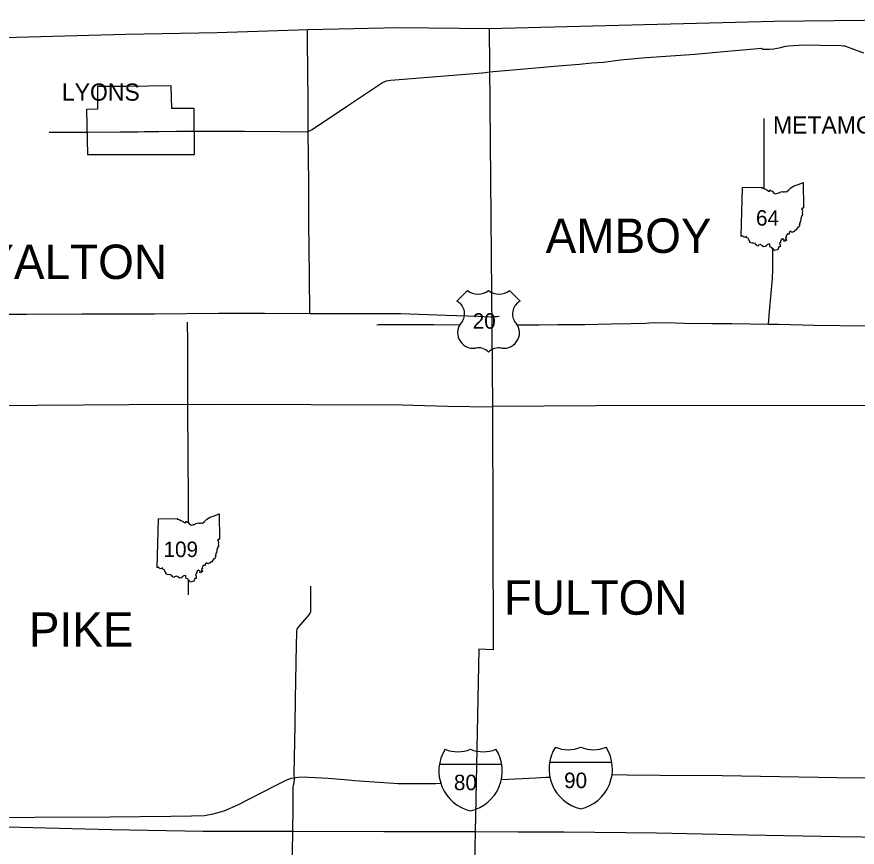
# Model space of a CAD drawing. Extents: x -232 to 448, y 619 to 1059.
# Drawn here: x 17.9 to 68.1, y 907.4 to 957 of the extents above; entities that cross this region are included whole.
import ezdxf

# ---------------------------------------------------------------- set-up
doc = ezdxf.new("R2010")
doc.units = 0
doc.layers.add('Default', color=7, linetype='Continuous')

msp = doc.modelspace()

# ---------------------------------------------------------------- linework, layer by layer
at = {"layer": 'Default'}
for p, q in [((61.207, 943.835), (61.289, 946.764)), ((61.207, 943.835), (61.289, 946.764)), ((44.856, 940.619), (44.222, 939.985)), ((44.856, 940.619), (44.222, 939.985)), ((48.012, 939.985), (47.377, 940.619)), ((48.012, 939.985), (47.377, 940.619)), ((26.318, 924.047), (26.4, 926.976)), ((26.318, 924.047), (26.4, 926.976)), ((43.182, 912.333), (46.902, 912.333)), ((49.765, 912.456), (53.486, 912.456))]:
    msp.add_line(p, q, dxfattribs=at)
for points in [[(46.162, 956.25), (63.186, 956.696), (68.56, 956.753), (73.967, 956.956), (79.258, 956.939)], [(13.563, 955.63), (24.424, 955.929), (29.905, 956.011), (35.341, 956.203), (40.766, 956.311), (46.162, 956.25)], [(35.432, 939.244), (35.416, 941.492), (35.389, 944.667), (35.385, 946.985), (35.348, 950.103), (35.345, 951.921), (35.293, 955.53), (35.297, 956.202)], [(46.162, 956.25), (46.355, 933.706)], [(45.931, 953.639), (46.146, 953.666), (47.115, 953.752), (48.94, 953.916), (50.044, 954.004), (51.547, 954.133), (52.282, 954.199), (52.978, 954.249), (54.005, 954.393), (55.537, 954.524), (57.009, 954.628), (58.442, 954.735), (60.391, 954.902), (61.773, 955.025), (62.425, 955.086), (62.443, 955.057), (62.483, 955.033), (62.582, 955.024), (62.663, 955.025)], [(62.663, 955.025), (62.903, 955.025), (63.13, 955.046), (63.576, 955.123), (63.784, 955.175)], [(63.784, 955.175), (63.883, 955.199), (64.007, 955.218), (64.652, 955.27), (64.823, 955.279), (65.934, 955.264), (67.19, 955.243), (67.317, 955.229), (67.375, 955.221), (67.444, 955.198), (68.507, 954.806)], [(35.348, 950.103), (35.585, 950.225), (37.625, 951.605), (39.296, 952.722), (39.778, 953.029), (40.014, 953.133), (40.268, 953.172), (40.768, 953.216), (45.739, 953.614), (45.931, 953.639)], [(24.442, 952.798), (22.757, 952.796), (22.758, 951.433)], [(27.155, 952.839), (24.442, 952.798)], [(28.555, 948.739), (28.528, 951.49), (27.193, 951.475), (27.155, 952.839)], [(22.758, 951.433), (22.098, 951.427), (22.151, 948.731)], [(62.591, 946.734), (62.576, 949.299), (62.577, 950.888), (62.577, 950.894)], [(19.871, 950.071), (21.657, 950.076), (22.124, 950.078)], [(22.124, 950.078), (24.103, 950.085), (25.171, 950.096)], [(25.171, 950.096), (25.552, 950.1)], [(25.552, 950.1), (25.825, 950.103), (26.04, 950.105)], [(26.04, 950.105), (26.417, 950.109)], [(26.417, 950.109), (27.466, 950.119), (28.569, 950.132)], [(28.569, 950.132), (29.048, 950.138), (31.528, 950.123), (33.646, 950.109), (35.175, 950.088), (35.348, 950.103)], [(22.151, 948.731), (28.555, 948.739)], [(61.289, 946.764), (62.425, 946.783), (62.408, 946.747), (62.515, 946.74), (62.629, 946.677), (62.725, 946.638), (62.843, 946.545), (62.913, 946.546), (62.943, 946.622), (62.997, 946.563), (63.061, 946.553), (63.172, 946.412), (63.263, 946.382), (63.373, 946.43), (63.455, 946.438), (63.515, 946.485), (63.671, 946.526), (63.714, 946.502), (63.797, 946.507), (63.838, 946.525), (63.91, 946.509), (64.037, 946.615), (64.168, 946.741), (64.368, 946.859), (64.668, 946.971), (64.905, 947.072), (64.939, 945.552)], [(61.289, 946.764), (62.425, 946.783), (62.408, 946.747), (62.515, 946.74), (62.629, 946.677), (62.725, 946.638), (62.843, 946.545), (62.913, 946.546), (62.943, 946.622), (62.997, 946.563), (63.061, 946.553), (63.172, 946.412), (63.263, 946.382), (63.373, 946.43), (63.455, 946.438), (63.515, 946.485), (63.671, 946.526), (63.714, 946.502), (63.797, 946.507), (63.838, 946.525), (63.91, 946.509), (64.037, 946.615), (64.168, 946.741), (64.368, 946.859), (64.668, 946.971), (64.905, 947.072), (64.939, 945.552)], [(64.939, 945.552), (64.904, 945.53), (64.85, 945.54), (64.813, 945.498), (64.859, 945.427), (64.88, 945.352), (64.861, 945.269), (64.88, 945.2), (64.867, 945.143), (64.833, 945.086), (64.821, 945.032), (64.792, 944.975), (64.794, 944.943), (64.766, 944.918), (64.772, 944.823), (64.757, 944.77), (64.762, 944.724), (64.717, 944.713), (64.728, 944.675), (64.699, 944.646), (64.705, 944.596), (64.673, 944.564), (64.704, 944.5), (64.679, 944.48), (64.658, 944.403), (64.6, 944.387), (64.485, 944.245), (64.444, 944.192), (64.398, 944.178), (64.373, 944.123), (64.316, 944.123), (64.231, 944.085), (64.176, 944.15), (64.079, 944.071), (64.068, 943.98), (63.946, 943.983), (63.951, 943.937), (63.923, 943.923), (63.898, 943.877), (63.913, 943.795), (63.856, 943.774), (63.863, 943.726), (63.899, 943.697), (63.915, 943.606), (63.855, 943.624), (63.805, 943.547), (63.754, 943.565), (63.77, 943.631), (63.684, 943.709), (63.602, 943.646), (63.559, 943.546), (63.559, 943.478), (63.498, 943.438), (63.537, 943.342), (63.53, 943.277), (63.531, 943.215), (63.454, 943.217), (63.408, 943.049)], [(64.939, 945.552), (64.904, 945.53), (64.85, 945.54), (64.813, 945.498), (64.859, 945.427), (64.88, 945.352), (64.861, 945.269), (64.88, 945.2), (64.867, 945.143), (64.833, 945.086), (64.821, 945.032), (64.792, 944.975), (64.794, 944.943), (64.766, 944.918), (64.772, 944.823), (64.757, 944.77), (64.762, 944.724), (64.717, 944.713), (64.728, 944.675), (64.699, 944.646), (64.705, 944.596), (64.673, 944.564), (64.704, 944.5), (64.679, 944.48), (64.658, 944.403), (64.6, 944.387), (64.485, 944.245), (64.444, 944.192), (64.398, 944.178), (64.373, 944.123), (64.316, 944.123), (64.231, 944.085), (64.176, 944.15), (64.079, 944.071), (64.068, 943.98), (63.946, 943.983), (63.951, 943.937), (63.923, 943.923), (63.898, 943.877), (63.913, 943.795), (63.856, 943.774), (63.863, 943.726), (63.899, 943.697), (63.915, 943.606), (63.855, 943.624), (63.805, 943.547), (63.754, 943.565), (63.77, 943.631), (63.684, 943.709), (63.602, 943.646), (63.559, 943.546), (63.559, 943.478), (63.498, 943.438), (63.537, 943.342), (63.53, 943.277), (63.531, 943.215), (63.454, 943.217), (63.408, 943.049)], [(63.408, 943.049), (63.276, 943.016), (63.184, 942.997), (63.151, 943.074), (63.085, 943.114), (63.042, 943.191), (62.948, 943.201), (62.926, 943.307), (62.915, 943.393), (62.786, 943.371), (62.75, 943.319), (62.704, 943.305), (62.678, 943.252), (62.615, 943.248), (62.548, 943.223), (62.504, 943.275), (62.395, 943.327), (62.345, 943.353), (62.242, 943.312), (62.22, 943.262), (62.138, 943.284), (62.118, 943.339), (62.069, 943.356), (62.058, 943.414), (61.951, 943.445), (61.87, 943.433), (61.727, 943.48), (61.718, 943.556), (61.669, 943.65), (61.643, 943.715), (61.553, 943.765), (61.534, 943.842), (61.505, 943.839), (61.479, 943.808), (61.378, 943.794), (61.338, 943.825), (61.281, 943.879), (61.207, 943.835)], [(63.408, 943.049), (63.276, 943.016), (63.184, 942.997), (63.151, 943.074), (63.085, 943.114), (63.042, 943.191), (62.948, 943.201), (62.926, 943.307), (62.915, 943.393), (62.786, 943.371), (62.75, 943.319), (62.704, 943.305), (62.678, 943.252), (62.615, 943.248), (62.548, 943.223), (62.504, 943.275), (62.395, 943.327), (62.345, 943.353), (62.242, 943.312), (62.22, 943.262), (62.138, 943.284), (62.118, 943.339), (62.069, 943.356), (62.058, 943.414), (61.951, 943.445), (61.87, 943.433), (61.727, 943.48), (61.718, 943.556), (61.669, 943.65), (61.643, 943.715), (61.553, 943.765), (61.534, 943.842), (61.505, 943.839), (61.479, 943.808), (61.378, 943.794), (61.338, 943.825), (61.281, 943.879), (61.207, 943.835)], [(62.841, 938.614), (62.904, 939.38), (62.993, 940.459), (63.077, 941.341), (63.084, 941.517), (63.095, 941.696), (63.102, 943.098)], [(6.067, 939.179), (8.183, 939.197), (10.438, 939.168), (11.654, 939.194), (12.383, 939.195), (13.745, 939.193), (15.975, 939.201), (18.534, 939.209), (21.835, 939.226), (24.29, 939.226), (26.171, 939.23), (29.99, 939.259), (32.3, 939.253), (32.737, 939.252)], [(32.737, 939.252), (35.432, 939.244), (36.578, 939.244), (38.574, 939.25), (40.182, 939.243), (40.884, 939.242), (43.585, 939.15), (45.503, 939.08), (45.837, 939.068)], [(45.837, 939.068), (46.28, 939.052), (46.428, 939.05), (46.506, 939.062), (46.613, 939.069), (46.731, 939.089), (46.748, 939.09)], [(28.193, 926.739), (28.192, 927.873), (28.176, 931.034), (28.157, 933.292), (28.152, 935.057), (28.142, 937.555), (28.13, 938.727)], [(39.447, 938.573), (39.541, 938.583), (39.673, 938.589), (42.851, 938.577), (44.397, 938.567)], [(47.839, 938.562), (48.772, 938.567), (49.15, 938.57), (50.258, 938.584), (51.875, 938.577), (53.435, 938.615), (54.613, 938.651), (55.518, 938.656), (55.721, 938.688), (56.005, 938.698), (57.276, 938.676), (57.825, 938.671), (59.47, 938.649), (60.673, 938.643), (62.841, 938.614), (63.431, 938.604), (65.59, 938.555), (68.68, 938.499), (71.353, 938.44), (71.641, 938.442), (71.959, 938.47), (72.174, 938.49)], [(13.763, 933.752), (19.166, 933.771), (24.64, 933.81), (30.058, 933.825), (35.498, 933.8), (40.955, 933.797), (43.667, 933.715), (46.355, 933.677)], [(46.355, 933.677), (46.402, 919.16), (45.539, 919.191), (45.319, 908.301)], [(46.355, 933.706), (52.547, 933.741), (63.267, 933.761), (68.715, 933.752), (74.09, 933.66), (77.553, 933.663), (79.515, 933.612)], [(46.355, 933.706), (46.355, 933.677)], [(26.4, 926.976), (27.536, 926.995), (27.519, 926.96), (27.626, 926.952), (27.74, 926.89), (27.836, 926.85), (27.954, 926.757), (28.025, 926.758), (28.054, 926.835), (28.108, 926.776), (28.172, 926.765), (28.283, 926.625), (28.375, 926.595), (28.484, 926.643), (28.566, 926.65), (28.626, 926.698), (28.782, 926.739), (28.825, 926.714), (28.908, 926.719), (28.949, 926.737), (29.021, 926.721), (29.148, 926.828), (29.279, 926.953), (29.479, 927.072), (29.779, 927.184), (30.016, 927.284), (30.05, 925.764)], [(26.4, 926.976), (27.536, 926.995), (27.519, 926.96), (27.626, 926.952), (27.74, 926.89), (27.836, 926.85), (27.954, 926.757), (28.025, 926.758), (28.054, 926.835), (28.108, 926.776), (28.172, 926.765), (28.283, 926.625), (28.375, 926.595), (28.484, 926.643), (28.566, 926.65), (28.626, 926.698), (28.782, 926.739), (28.825, 926.714), (28.908, 926.719), (28.949, 926.737), (29.021, 926.721), (29.148, 926.828), (29.279, 926.953), (29.479, 927.072), (29.779, 927.184), (30.016, 927.284), (30.05, 925.764)], [(30.05, 925.764), (30.015, 925.743), (29.961, 925.753), (29.924, 925.71), (29.97, 925.639), (29.991, 925.564), (29.972, 925.481), (29.991, 925.413), (29.978, 925.356), (29.944, 925.299), (29.932, 925.245), (29.903, 925.188), (29.905, 925.156), (29.878, 925.13), (29.883, 925.035), (29.869, 924.982), (29.873, 924.937), (29.828, 924.925), (29.839, 924.888), (29.81, 924.859), (29.816, 924.809), (29.784, 924.777), (29.815, 924.713), (29.79, 924.693), (29.769, 924.615), (29.711, 924.6), (29.596, 924.458), (29.555, 924.404), (29.509, 924.391), (29.484, 924.336), (29.428, 924.335), (29.342, 924.297), (29.287, 924.363), (29.19, 924.284), (29.179, 924.193), (29.057, 924.195), (29.062, 924.149), (29.034, 924.136), (29.01, 924.09), (29.024, 924.007), (28.967, 923.986), (28.974, 923.939), (29.01, 923.91), (29.027, 923.818), (28.966, 923.837), (28.916, 923.76), (28.865, 923.778), (28.881, 923.843), (28.795, 923.921), (28.713, 923.859), (28.67, 923.758), (28.67, 923.691), (28.609, 923.65), (28.648, 923.555), (28.641, 923.489), (28.642, 923.427), (28.566, 923.429), (28.519, 923.261)], [(30.05, 925.764), (30.015, 925.743), (29.961, 925.753), (29.924, 925.71), (29.97, 925.639), (29.991, 925.564), (29.972, 925.481), (29.991, 925.413), (29.978, 925.356), (29.944, 925.299), (29.932, 925.245), (29.903, 925.188), (29.905, 925.156), (29.878, 925.13), (29.883, 925.035), (29.869, 924.982), (29.873, 924.937), (29.828, 924.925), (29.839, 924.888), (29.81, 924.859), (29.816, 924.809), (29.784, 924.777), (29.815, 924.713), (29.79, 924.693), (29.769, 924.615), (29.711, 924.6), (29.596, 924.458), (29.555, 924.404), (29.509, 924.391), (29.484, 924.336), (29.428, 924.335), (29.342, 924.297), (29.287, 924.363), (29.19, 924.284), (29.179, 924.193), (29.057, 924.195), (29.062, 924.149), (29.034, 924.136), (29.01, 924.09), (29.024, 924.007), (28.967, 923.986), (28.974, 923.939), (29.01, 923.91), (29.027, 923.818), (28.966, 923.837), (28.916, 923.76), (28.865, 923.778), (28.881, 923.843), (28.795, 923.921), (28.713, 923.859), (28.67, 923.758), (28.67, 923.691), (28.609, 923.65), (28.648, 923.555), (28.641, 923.489), (28.642, 923.427), (28.566, 923.429), (28.519, 923.261)], [(28.519, 923.261), (28.387, 923.229), (28.295, 923.21), (28.262, 923.286), (28.196, 923.326), (28.154, 923.403), (28.059, 923.414), (28.037, 923.519), (28.026, 923.605), (27.897, 923.584), (27.861, 923.532), (27.816, 923.518), (27.789, 923.465), (27.726, 923.46), (27.659, 923.435), (27.616, 923.487), (27.506, 923.539), (27.456, 923.566), (27.353, 923.524), (27.331, 923.475), (27.249, 923.497), (27.23, 923.552), (27.18, 923.568), (27.169, 923.627), (27.062, 923.658), (26.981, 923.645), (26.838, 923.692), (26.829, 923.769), (26.78, 923.863), (26.755, 923.928), (26.664, 923.977), (26.646, 924.054), (26.616, 924.052), (26.59, 924.021), (26.489, 924.006), (26.449, 924.038), (26.393, 924.092), (26.318, 924.047)], [(28.519, 923.261), (28.387, 923.229), (28.295, 923.21), (28.262, 923.286), (28.196, 923.326), (28.154, 923.403), (28.059, 923.414), (28.037, 923.519), (28.026, 923.605), (27.897, 923.584), (27.861, 923.532), (27.816, 923.518), (27.789, 923.465), (27.726, 923.46), (27.659, 923.435), (27.616, 923.487), (27.506, 923.539), (27.456, 923.566), (27.353, 923.524), (27.331, 923.475), (27.249, 923.497), (27.23, 923.552), (27.18, 923.568), (27.169, 923.627), (27.062, 923.658), (26.981, 923.645), (26.838, 923.692), (26.829, 923.769), (26.78, 923.863), (26.755, 923.928), (26.664, 923.977), (26.646, 924.054), (26.616, 924.052), (26.59, 924.021), (26.489, 924.006), (26.449, 924.038), (26.393, 924.092), (26.318, 924.047)], [(28.189, 922.443), (28.192, 923.335)], [(34.329, 902.898), (34.378, 905.827), (34.423, 908.325), (34.435, 909.747), (34.452, 910.711), (34.444, 910.954), (34.455, 911.077), (34.494, 911.216), (34.521, 911.481), (34.513, 911.732), (34.569, 914.671), (34.588, 916.21), (34.649, 919.474), (34.656, 920.146), (34.664, 920.282), (34.692, 920.398), (34.766, 920.505), (35.396, 921.254), (35.464, 921.345), (35.497, 921.439), (35.495, 921.597), (35.501, 922.15), (35.491, 922.96)], [(16.297, 909.149), (19.012, 909.164), (23.507, 909.198), (27.134, 909.23), (28.367, 909.242), (29.139, 909.274), (29.657, 909.361), (30.331, 909.551), (31.132, 909.913), (33.428, 911.082), (34.059, 911.393), (34.343, 911.492), (34.733, 911.556), (35.112, 911.577), (35.36, 911.555), (36.544, 911.495), (37.741, 911.393), (38.116, 911.358), (39.587, 911.253), (40.723, 911.178), (41.057, 911.175), (42.066, 911.174), (42.943, 911.187), (43.231, 911.208)], [(46.888, 911.423), (48.933, 911.512), (49.531, 911.552), (49.806, 911.566)], [(53.508, 911.721), (54.391, 911.705), (56.352, 911.684), (60.081, 911.649), (65.807, 911.561), (66.915, 911.543), (69.643, 911.509), (70.722, 911.472)], [(45.319, 908.301), (39.864, 908.285), (34.454, 908.323), (29.058, 908.316), (23.567, 908.418), (18.126, 908.554), (12.707, 908.674)], [(45.319, 908.301), (45.264, 905.553), (44.888, 886.545), (44.577, 870.248)], [(77.947, 907.809), (72.504, 907.924), (67.081, 908.001), (61.61, 908.099), (56.148, 908.205), (50.625, 908.265), (47.884, 908.282), (45.319, 908.301)]]:
    msp.add_lwpolyline(points, dxfattribs=at)
for centre, radius, start, end in [((45.487, 941.42), 1.019, 231.813, 308.187), ((45.487, 941.42), 1.019, 231.813, 308.187), ((46.747, 941.42), 1.019, 231.813, 308.187), ((46.747, 941.42), 1.019, 231.813, 308.187), ((43.826, 939.219), 0.862, 329.1175, 62.6108), ((43.826, 939.219), 0.862, 329.1175, 62.6108), ((48.408, 939.219), 0.862, 117.3892, 210.8825), ((48.408, 939.219), 0.862, 117.3892, 210.8825), ((45.2, 938.097), 0.93, 133.0046, 278.7282), ((45.2, 938.097), 0.93, 133.0046, 278.7282), ((47.034, 938.097), 0.93, 261.2718, 46.9954), ((47.034, 938.097), 0.93, 261.2718, 46.9954), ((45.512, 936.363), 0.832, 43.4177, 101.8742), ((45.512, 936.363), 0.832, 43.4177, 101.8742), ((46.739, 936.308), 0.883, 79.9613, 134.7468), ((46.739, 936.308), 0.883, 79.9613, 134.7468), ((52.176, 912.047), 2.445, 147.8216, 256.9941), ((52.176, 912.047), 2.445, 147.8216, 256.9941), ((50.866, 915.146), 1.951, 247.0848, 292.9105), ((50.866, 915.146), 1.951, 247.0848, 292.9105), ((51.075, 912.047), 2.445, 283.0065, 32.1787), ((52.385, 915.146), 1.951, 247.0916, 292.9084), ((51.075, 912.047), 2.445, 283.0065, 32.1787), ((52.385, 915.146), 1.951, 247.0916, 292.9084), ((45.592, 911.923), 2.445, 147.8216, 256.9941), ((45.592, 911.923), 2.445, 147.8216, 256.9941), ((44.282, 915.022), 1.951, 247.0848, 292.9105), ((44.282, 915.022), 1.951, 247.0848, 292.9105), ((44.491, 911.923), 2.445, 283.0065, 32.1787), ((45.801, 915.023), 1.951, 247.0916, 292.9084), ((44.491, 911.923), 2.445, 283.0065, 32.1787), ((45.801, 915.023), 1.951, 247.0916, 292.9084)]:
    msp.add_arc(centre, radius, start, end, dxfattribs=at)

# ---------------------------------------------------------------- texts
for s, height, p in [('LYONS', 1.026, (20.627, 951.949)), ('METAMORA', 1.026, (63.11, 949.986)), ('64', 0.9234, (62.093, 944.488)), ('AMBOY', 2.052, (49.528, 942.86)), ('ROYALTON', 2.052, (11.815, 941.303)), ('20', 0.9234, (45.172, 938.335)), ('109', 0.9234, (26.699, 924.7)), ('FULTON', 2.052, (47.028, 921.257)), ('PIKE', 2.052, (18.65, 919.354)), ('90', 0.9234, (50.631, 910.904)), ('80', 0.9234, (44.047, 910.78))]:
    msp.add_text(s, height=height, dxfattribs=at).set_placement(p)

doc.saveas('drawing.dxf')
